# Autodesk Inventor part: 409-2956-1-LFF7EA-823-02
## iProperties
Created: 2010-11
Part Number: 409-2956-1-LFF7EA-823-02
Material: 3/8" OD TUBE - SS
Document SubType Name: Modeling
Designer: S. Boerckel
Engineer: Steve Boerckel
Mass: 285.633 g
Surface Area: 619.161 cm^2
Volume: 35.3507 cm^3
Density: 8.08 g/cm^3
Description: PRESSURE DIFF TUBE
Length: 59.928 in
Author: S. Boerckel
Revision Number: 0
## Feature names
1. Sweep3
